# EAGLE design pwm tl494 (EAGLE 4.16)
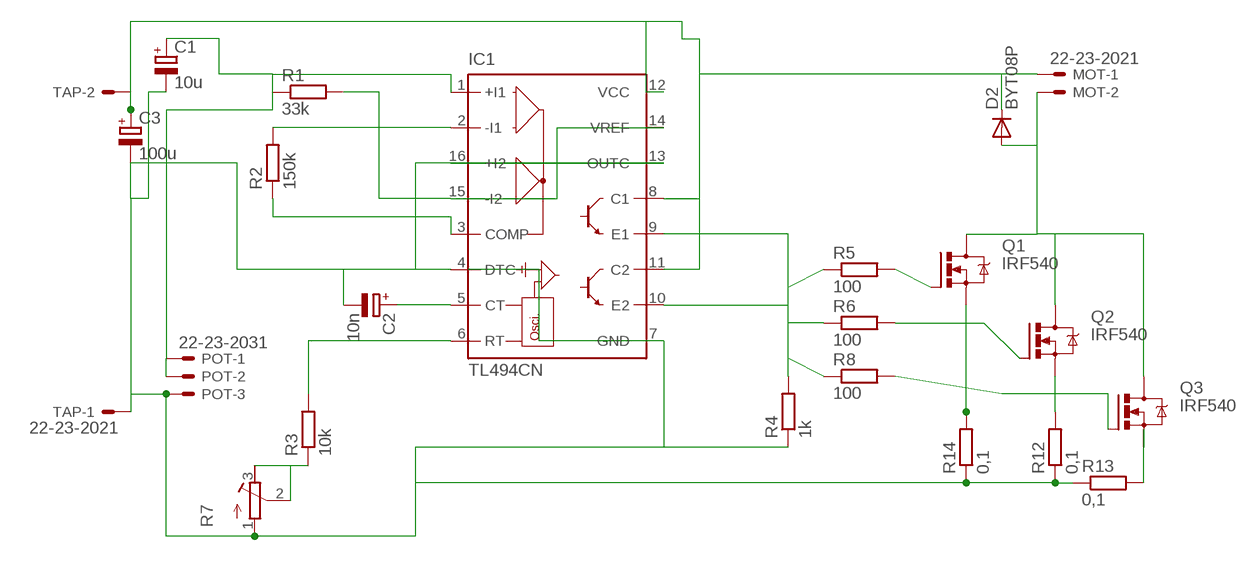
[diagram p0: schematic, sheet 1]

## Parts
C1  10u  CPOL-EUE3.5-10  [E3,5-10]
C2  10n  CPOL-EUE3.5-10  [E3,5-10]
C3  100u  CPOL-EUE3.5-10  [E3,5-10]
D2  BYT08P  [TO220ACS]
IC1  TL494CN  [DIL16]
MOT  22-23-2021  [22-23-2021]
POT  22-23-2031  [22-23-2031]
Q1  IRF540  [TO220BV]
Q2  IRF540  [TO220BV]
Q3  IRF540  [TO220BV]
R1  33k  R-EU_0204/7  [0204/7]
R2  150k  R-EU_0204/7  [0204/7]
R3  10k  R-EU_0204/7  [0204/7]
R4  1k  R-EU_0204/7  [0204/7]
R5  100  R-EU_0204/7  [0204/7]
R6  100  R-EU_0204/7  [0204/7]
R7  R-TRIMM3339P  [RTRIM3339P]
R8  100  R-EU_0204/7  [0204/7]
R12  0,1  R-EU_0922V  [0922V]
R13  0,1  R-EU_0922V  [0922V]
R14  0,1  R-EU_0922V  [0922V]
TAP  22-23-2021  [22-23-2021]

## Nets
N$1: IC1.14(VREF) IC1.15(-I2) R1.2
N$2: Q1.S R14.2
N$3: R3.1 R7.2(S) R7.3(A)
N$4: IC1.2(-I1) R2.2
N$5: IC1.3(COMP) R2.1
N$6: C1.+ IC1.1(+I1) POT.1 POT.2 R1.1
N$7: C3.+ D2.C IC1.8(C1) IC1.11(C2) IC1.12(VCC) MOT.1 TAP.2
N$9: IC1.6(RT) R3.2
N$10: Q2.S R12.2
N$11: Q3.S R13.2
N$12: Q3.G R8.2
N$13: C2.+ IC1.5(CT)
N$14: Q2.G R6.2
N$15: IC1.9(E1) IC1.10(E2) R4.2 R5.1 R6.1 R8.1
N$16: Q1.G R5.2
N$17: D2.A MOT.2 Q1.D Q2.D Q3.D
N$19: C1.- C2.- C3.- IC1.4(DTC) IC1.7(GND) IC1.13(OUTC) IC1.16(+I2) POT.3 R4.1 R7.1(E) R12.1 R13.1 R14.1 TAP.1

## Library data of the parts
C1-C3 = rcl:CPOL-EU: POLARIZED CAPACITOR, European symbol
D2 = diode:BYT08P: DIODE
IC1 = linear:TL494*: SWITCHMODE Pulse Width Modulation Control Circuit NCV494B http://onsemi.com tl494-d.pdf
MOT TAP = con-molex:22-23-2021: .100" (2.54mm) Center Header - 2 Pin
POT = con-molex:22-23-2031: .100" (2.54mm) Center Header - 3 Pin
Q1-Q3 = transistor-power:IRF540: HEXFET Power MOSFET
R1-R6 R8 R12-R14 = rcl:R-EU_: RESISTOR, European symbol
R7 = rcl:R-TRIMM: Trimm resistor

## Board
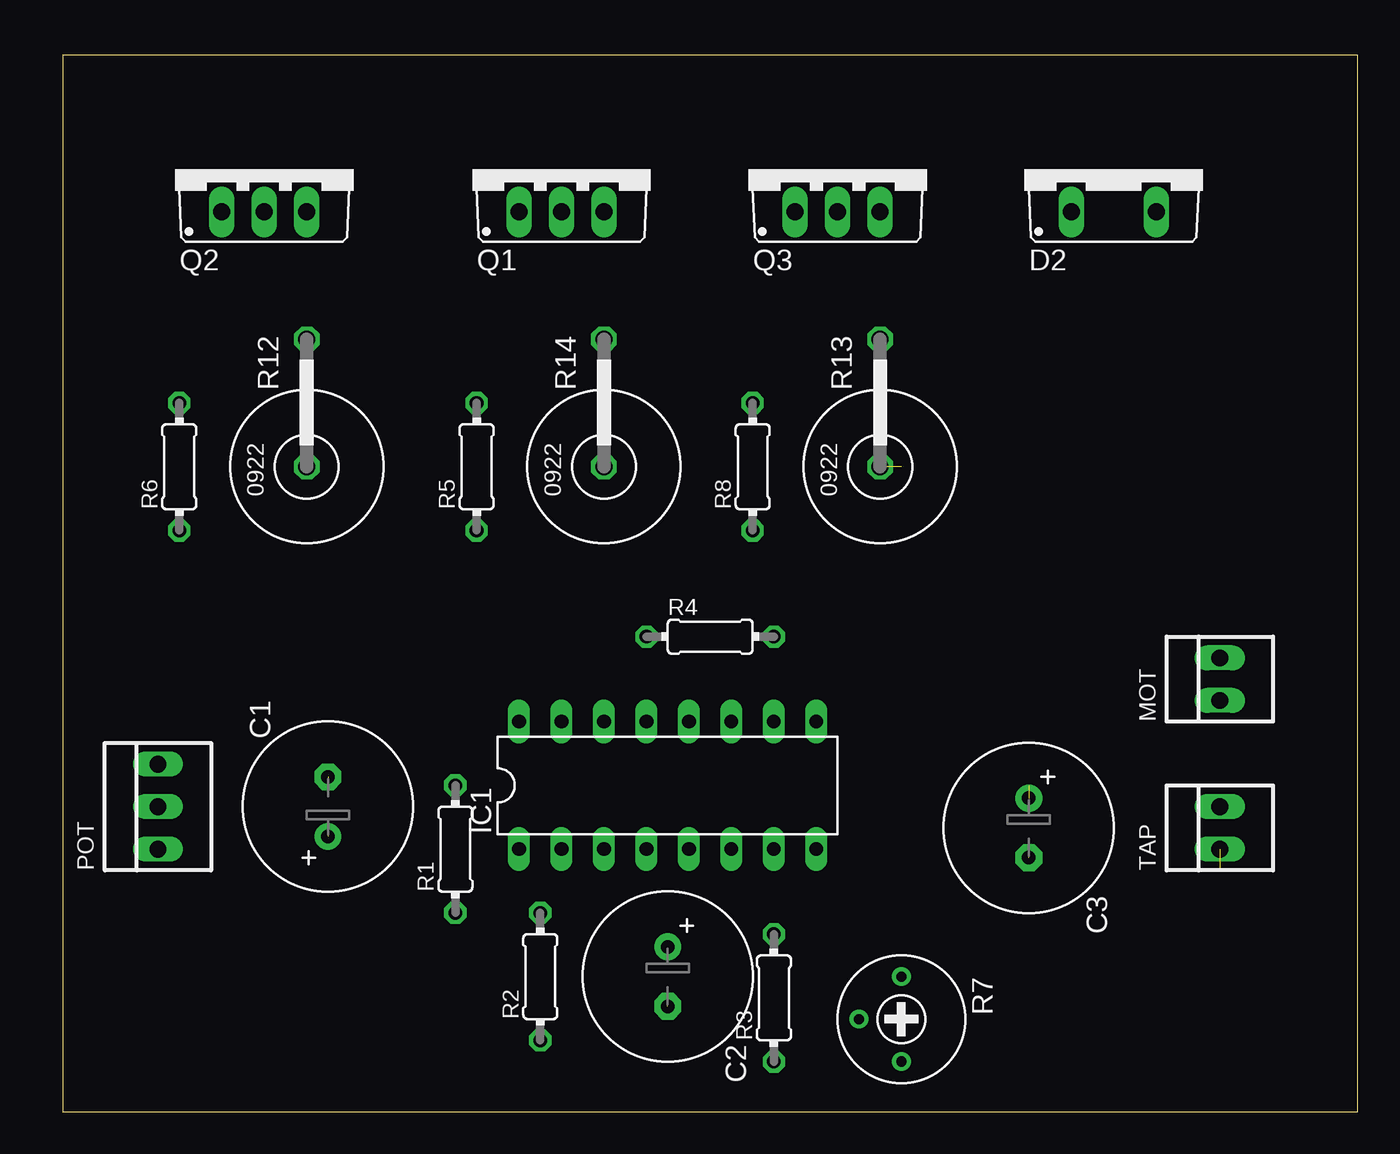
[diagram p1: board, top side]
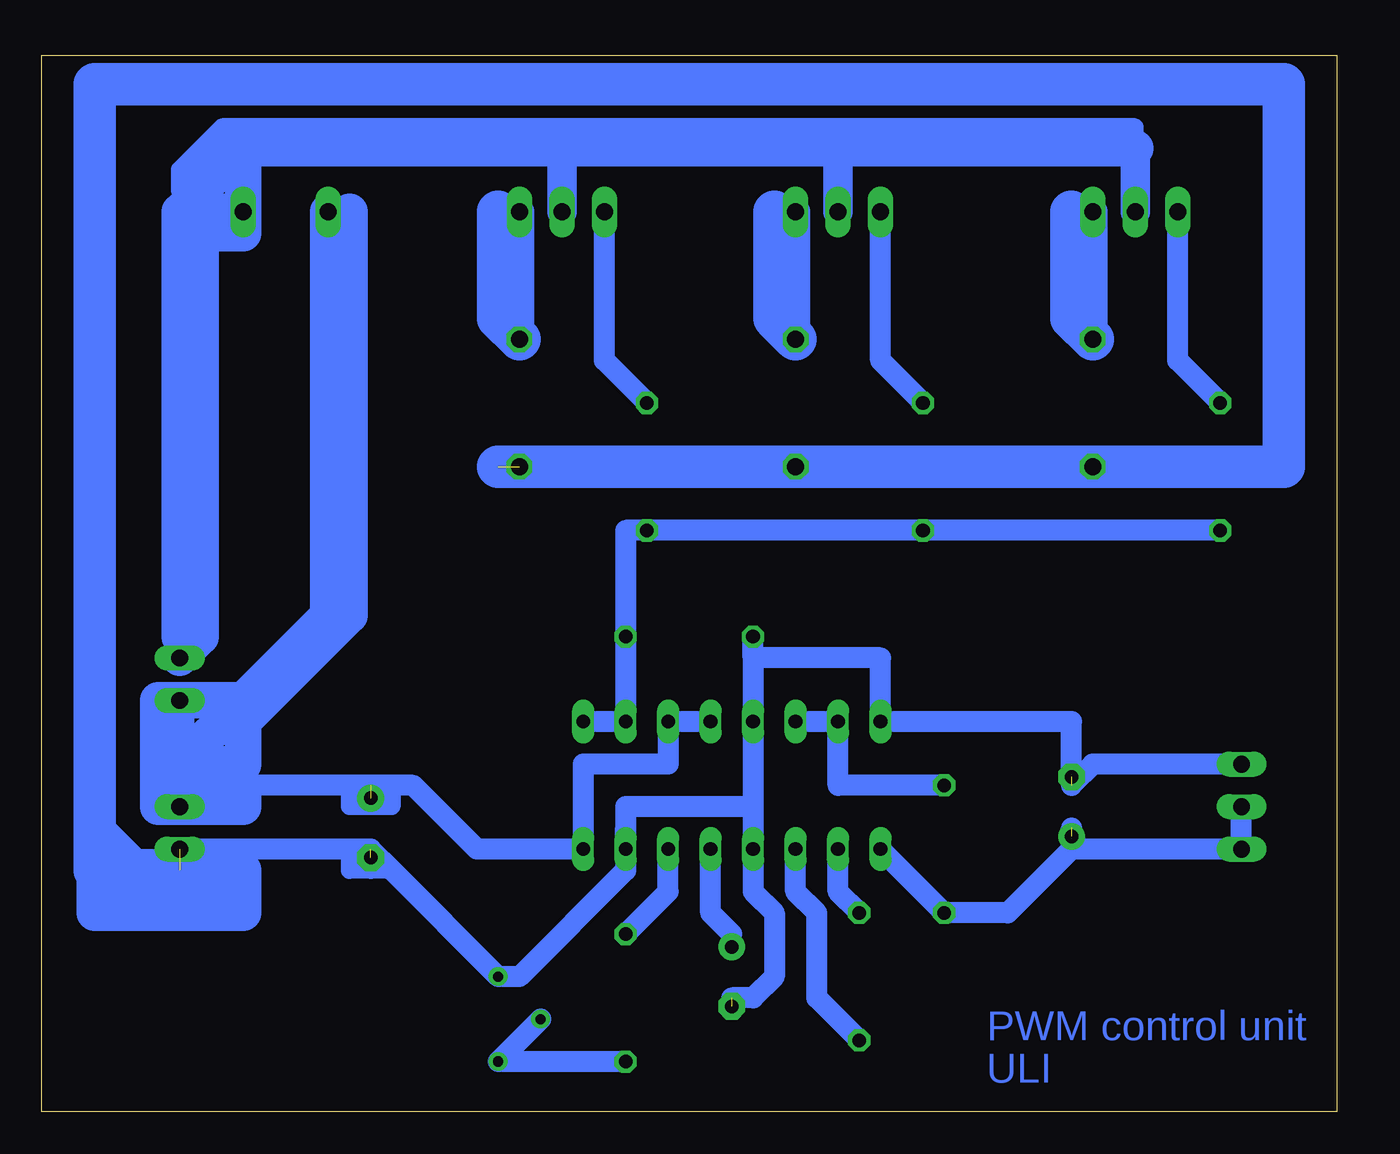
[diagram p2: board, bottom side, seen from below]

Size 77.45 x 63.17 mm. Coordinates in mm from the lower left corner, seen from the top.
Outline: 0,0 77.45,0 77.45,63.17 0,63.17 0,0
Copper layers (1*16): Top 0.035mm / dielectric 1.5mm / Bottom 0.035mm
Design rules "default": minimum track width 10mil, minimum drill 24mil, track to track 8mil, track to pad 8mil, pad to pad 8mil, via to via 8mil, smd to smd 8mil, copper to edge 40mil, drill to drill 8mil, minimum pad ring 10mil, minimum via ring 8mil, stop-mask expansion 4mil, vias tented up to drill 0mil, thermal gap 10mil

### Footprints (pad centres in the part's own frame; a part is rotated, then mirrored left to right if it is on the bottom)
E3,5-10 = drill 0.813 pad 1.6 round: + -1.778,0 | drill 0.813 pad 1.6 octagon: - 1.778,0
TO220ACS = drill 1.016 long: A 2.54,-2.54; C -2.54,-2.54
DIL16 = drill 0.813 long: 1 -8.89,-3.81; 2 -6.35,-3.81; 3 -3.81,-3.81; 4 -1.27,-3.81; 5 1.27,-3.81; 6 3.81,-3.81; 7 6.35,-3.81; 8 8.89,-3.81; 9 8.89,3.81; 10 6.35,3.81; 11 3.81,3.81; 12 1.27,3.81; 13 -1.27,3.81; 14 -3.81,3.81; 15 -6.35,3.81; 16 -8.89,3.81
22-23-2021 = drill 1 long: 1 -1.27,0; 2 1.27,0
22-23-2031 = drill 1 long: 1 -2.54,0; 2 0,0; 3 2.54,0
TO220BV = drill 1.016 long: D 0,-2.54; G -2.54,-2.54; S 2.54,-2.54
0204/7 = drill 0.813 octagon: 1 -3.81,0; 2 3.81,0
RTRIM3339P = drill 0.61 round: 1 -2.54,0; 2 0,-2.54; 3 2.54,0
0922V = drill 1.016 octagon: 1 -5.08,0; 2 2.54,0

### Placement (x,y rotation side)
C1  15.87,18.25 90 top
C2  36.19,8.09 270 top
C3  57.78,16.98 270 top
D2  62.86,56.35 0 top
IC1  36.19,19.52 0 top
MOT  69.21,25.87 90 top
POT  5.71,18.25 90 top
Q1  29.84,56.35 0 top
Q2  12.06,56.35 0 top
Q3  46.35,56.35 0 top
R1  23.49,15.71 90 top
R2  28.57,8.09 90 top
R3  42.54,6.82 90 top
R4  38.73,28.41 0 top
R5  24.76,38.57 90 top
R6  6.98,38.57 90 top
R7  50.16,5.55 270 top
R8  41.27,38.57 90 top
R12  14.6,43.65 90 top
R13  48.89,43.65 90 top
R14  32.38,43.65 90 top
TAP  69.21,16.98 90 top

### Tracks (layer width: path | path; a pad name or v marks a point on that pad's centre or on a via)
N$1
  Bottom 1.27: R1.2 29.84,19.52 IC1.15 IC1.14
N$2
  Bottom 1.778: R14.2 Q1.S
  Bottom 2.54: R14.2 33.65,47.46 33.65,53.81
N$3
  Bottom 1.27: R7.2 R7.3 R3.1
N$4
  Bottom 1.27: IC1.2 29.84,13.17 R2.2
N$5
  Bottom 1.27: IC1.3 32.38,13.17 31.11,11.9 31.11,6.82 R2.1
N$6  (1 unrouted)
  Bottom 1.27: IC1.1 R1.1 19.68,11.9 15.87,15.71 | 15.87,15.71 15.87,16.98 | 15.87,15.71 POT.1 POT.2
N$7  (1 unrouted)
  Bottom 1.016: 57.78,19.52 57.78,18.25 | 57.78,18.25 59.05,18.25 59.05,19.52 56.51,19.52 56.51,18.25 57.78,18.25
  Bottom 1.27: TAP.2 67.94,19.52 65.4,19.52 59.05,19.52 57.78,19.52 56.51,19.52 55.24,19.52 51.43,15.71 IC1.8 45.08,20.79 40,20.79 IC1.11 IC1.12
  Bottom 1.778: TAP.2 MOT.1 65.4,24.6
  Bottom 2.184: D2.C 60.32,29.68 65.4,24.6 | 65.4,24.6 70.48,24.6 70.48,18.25 65.4,18.25 65.4,19.52 | 65.4,24.6 65.4,23.33 | 65.4,23.33 65.4,20.79 67.94,20.79 67.94,22.06 66.67,23.33 | 65.4,23.33 59.05,29.68 59.05,53.81
N$9
  Bottom 1.27: R3.2 40,13.17 IC1.6
N$10
  Bottom 1.778: R12.2 Q2.S
  Bottom 2.54: R12.2 15.87,47.46 15.87,53.81
N$11
  Bottom 1.778: R13.2 Q3.S
  Bottom 2.54: R13.2 50.16,47.46 50.16,53.81
N$12
  Bottom 1.27: R8.2 43.81,44.92 Q3.G
N$13
  Bottom 0.254: 36.19,9.36 C2.+ 36.19,10.63
  Bottom 1.27: 36.19,10.63 37.46,11.9 IC1.5
N$14
  Bottom 1.27: R6.2 9.52,44.92 Q2.G
N$15
  Bottom 1.27: R6.1 R5.1 R8.1 42.54,34.76 R4.2 IC1.10 IC1.9
N$16
  Bottom 1.27: R5.2 27.3,44.92 Q1.G
N$17
  Bottom 0.254: 69.21,53.81 69.21,55.08
  Bottom 1.016: 12.06,57.62 12.06,58.89 65.4,58.89 | 65.4,57.62 65.4,58.89 | 65.4,58.89 66.67,58.89 | 66.67,58.89 69.21,56.35 69.21,55.08 66.67,57.62 66.67,58.89
  Bottom 1.778: 69.21,28.41 MOT.2 | 69.21,53.81 66.67,53.81 | Q2.D 12.06,57.62 29.84,57.62 | 29.84,57.62 Q1.D | 46.35,57.62 Q3.D | 29.84,57.62 46.35,57.62 | 65.4,56.35 65.4,57.62 46.35,57.62
  Bottom 2.184: 12.06,57.62 65.4,57.62 69.21,53.81 69.21,28.41 | 66.67,53.81 D2.A 65.4,56.35 65.4,52.54 67.94,52.54 | MOT.2 67.94,28.41 67.94,51.27
N$19  (5 unrouted)
  Bottom 1.016: 56.51,14.44 57.78,14.44 | 57.78,14.44 59.05,14.44 59.05,15.71 57.78,14.44
  Bottom 1.27: TAP.1 59.05,15.71 57.78,15.71 56.51,14.44 R7.1 48.89,8.09 42.54,14.44 IC1.7 | 36.19,6.82 34.92,6.82 33.65,8.09 33.65,11.9 34.92,13.17 IC1.4 34.92,18.25 | 34.92,18.25 IC1.13 34.92,27.14 | POT.3 14.6,20.79 15.87,19.52 15.87,23.33 IC1.16 27.3,27.14 34.92,27.14 | 34.92,27.14 R4.1 | IC1.7 42.54,16.98 | IC1.7 42.54,18.25 34.92,18.25
  Bottom 1.778: R12.1 R14.1 50.16,38.57
  Bottom 2.184: 65.4,14.44 65.4,11.9 74.29,11.9 74.29,14.44 73.02,14.44 73.02,13.17 66.67,13.17 66.67,14.44 69.21,14.44 71.75,14.44 74.29,16.98
  Bottom 2.54: 50.16,38.57 R12.1 3.17,38.57 3.17,61.43 74.29,61.43 74.29,16.98 74.29,14.44 69.21,14.44

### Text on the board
Bottom: PWM control unit | ULI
